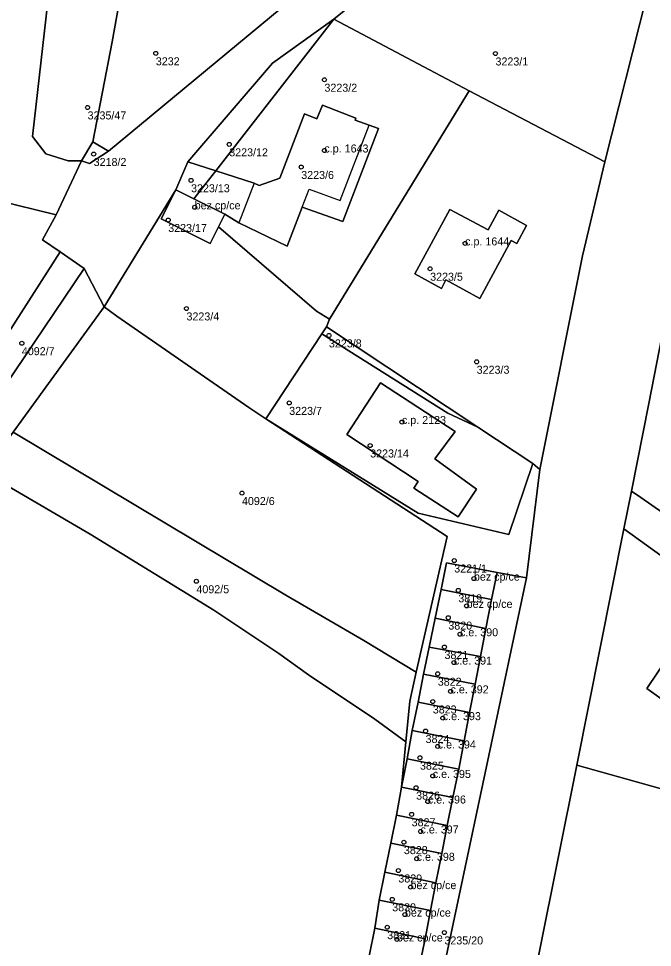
# Model space of a CAD drawing. Extents: x -878211 to -870363, y -1058464 to -1052522.
# Drawn here: x -875140.3 to -875061.1, y -1056719.1 to -1056603.1 of the extents above; entities that cross this region are included whole.
import ezdxf

# ---------------------------------------------------------------- set-up
doc = ezdxf.new("R2010")
doc.units = 0
for name, color, linetype in [('Definiční body', 7, 'Continuous'), ('Polygon budovy', 7, 'Continuous'), ('Polygon parcely', 7, 'Continuous')]:
    doc.layers.add(name, color=color, linetype=linetype)

msp = doc.modelspace()

# ---------------------------------------------------------------- linework, layer by layer
at = {"layer": 'Definiční body'}
for centre in [(-875123.14, -1056607.45994), (-875080.72, -1056607.47994), (-875102.08, -1056610.75994), (-875131.66, -1056614.21994), (-875113.97, -1056618.82994), (-875130.9, -1056620.03994), (-875102.08, -1056619.58994), (-875104.98, -1056621.65994), (-875118.74, -1056623.31994), (-875118.28, -1056626.68994), (-875121.59, -1056628.27994), (-875084.51, -1056631.19994), (-875088.88, -1056634.36994), (-875119.31, -1056639.32994), (-875101.52, -1056642.69994), (-875139.87, -1056643.66994), (-875083.07, -1056645.98994), (-875106.48, -1056651.12994), (-875092.4, -1056653.50994), (-875096.37, -1056656.44994), (-875112.38, -1056662.38994), (-875085.87, -1056670.81994), (-875118.07, -1056673.40994), (-875083.41, -1056673.06994), (-875085.36, -1056674.53994), (-875084.32, -1056676.47994), (-875086.61, -1056677.94994), (-875085.15, -1056680.01994), (-875087.09, -1056681.61994), (-875085.91, -1056683.55994), (-875087.93, -1056684.95994), (-875086.33, -1056687.15994), (-875088.55, -1056688.42994), (-875087.3, -1056690.49994), (-875089.45, -1056692.10994), (-875087.93, -1056694.03994), (-875090.15, -1056695.44994), (-875088.55, -1056697.71994), (-875090.63, -1056699.18994), (-875089.17, -1056700.91994), (-875091.19, -1056702.51994), (-875090.08, -1056704.65994), (-875092.16, -1056705.99994), (-875090.56, -1056708.06994), (-875092.85, -1056709.53994), (-875091.33, -1056711.60994), (-875093.62, -1056713.13994), (-875092.02, -1056715.03994), (-875094.24, -1056716.61994), (-875087.1, -1056717.27994), (-875093.03, -1056718.14994)]:
    msp.add_circle(centre, 0.25, dxfattribs=at)
at = {"layer": 'Polygon budovy'}
for points in [[(-875098.17, -1056615.55), (-875102.34, -1056613.94), (-875103.02, -1056615.62), (-875104.57, -1056615.01), (-875107.67, -1056623.06), (-875110.23, -1056623.95), (-875110.84, -1056623.69), (-875112.76, -1056628.63), (-875106.72, -1056631.55), (-875104.85, -1056626.68), (-875103.98, -1056624.42), (-875100.12, -1056625.85), (-875096.51, -1056616.44), (-875098.25, -1056615.79)], [(-875120.62, -1056624.51), (-875122.46, -1056628.14), (-875116.34, -1056631.22), (-875115.29, -1056629.12), (-875114.51, -1056627.56), (-875118.38, -1056625.63)], [(-875086.4, -1056626.95), (-875090.81, -1056635.01), (-875087.48, -1056636.81), (-875086.9, -1056635.74), (-875082.66, -1056638.07), (-875078.75, -1056630.82), (-875078.05, -1056631.2), (-875076.84, -1056628.96), (-875080.32, -1056627.03), (-875081.64, -1056629.5)], [(-875095.06, -1056648.6), (-875099.29, -1056655.07), (-875090.38, -1056660.94), (-875090.93, -1056661.77), (-875085.38, -1056665.36), (-875083.1, -1056661.9), (-875088.29, -1056658.09), (-875085.76, -1056654.68)], [(-875086.83, -1056671.12), (-875087.51, -1056674.45), (-875081.22, -1056675.66), (-875080.52, -1056672.32)], [(-875088.24, -1056678.03), (-875081.93, -1056679.3), (-875081.22, -1056675.66), (-875087.51, -1056674.45)], [(-875088.99, -1056681.62), (-875082.61, -1056682.78), (-875081.93, -1056679.3), (-875088.24, -1056678.03)], [(-875046.32, -1056685), (-875044.88, -1056682.91), (-875046.64, -1056681.74), (-875048.06, -1056683.83), (-875056.14, -1056678.39), (-875061.81, -1056686.81), (-875059.04, -1056688.8), (-875059.07, -1056689.09), (-875048.31, -1056696.37), (-875048.14, -1056696.15), (-875045.19, -1056698.06), (-875039.56, -1056689.55)], [(-875088.99, -1056681.62), (-875089.73, -1056685.01), (-875083.27, -1056686.24), (-875082.61, -1056682.78)], [(-875090.36, -1056688.49), (-875083.97, -1056689.81), (-875083.27, -1056686.24), (-875089.73, -1056685.01)], [(-875084.65, -1056693.35), (-875083.97, -1056689.81), (-875090.36, -1056688.49), (-875091.11, -1056692.06)], [(-875091.75, -1056695.59), (-875085.31, -1056696.89), (-875084.65, -1056693.35), (-875091.11, -1056692.06)], [(-875091.75, -1056695.59), (-875092.44, -1056699.14), (-875086.03, -1056700.41), (-875085.31, -1056696.89)], [(-875093.1, -1056702.61), (-875086.74, -1056703.92), (-875086.03, -1056700.41), (-875092.44, -1056699.14)], [(-875093.1, -1056702.61), (-875093.77, -1056706.12), (-875087.41, -1056707.4), (-875086.74, -1056703.92)], [(-875094.52, -1056709.74), (-875088.16, -1056711.08), (-875087.41, -1056707.4), (-875093.77, -1056706.12)], [(-875094.52, -1056709.74), (-875095.25, -1056713.24), (-875088.82, -1056714.54), (-875088.16, -1056711.08)], [(-875095.8, -1056716.75), (-875089.5, -1056718.06), (-875088.82, -1056714.54), (-875095.25, -1056713.24)], [(-875095.8, -1056716.75), (-875096.5, -1056720.24), (-875090.24, -1056721.62), (-875089.5, -1056718.06)]]:
    msp.add_lwpolyline(points, close=True, dxfattribs=at)
at = {"layer": 'Polygon parcely'}
for points in [[(-874975.13, -1056393.67), (-874980.45, -1056410.63), (-874983.57, -1056424.89), (-875001.65, -1056483.66), (-875005.15, -1056492.08), (-875032.55, -1056540.02), (-875035.19, -1056534.63), (-875039.79, -1056543.8), (-875051.68, -1056572.91), (-875052.45, -1056574.91), (-875061.84, -1056600.38), (-875067.07, -1056621.01), (-875069.87, -1056632.77), (-875075.2, -1056659.42), (-875076.83, -1056672.97), (-875088.05, -1056725.8)], [(-875147.44, -1056651.53), (-875135.09, -1056632.27), (-875137.28, -1056630.77), (-875135.57, -1056627.63), (-875150.54, -1056623.98)], [(-875079.85, -1056742.65), (-875070.58, -1056696.36), (-875064.69, -1056666.87), (-875063.74, -1056662.13), (-875061.56, -1056651.21), (-875058, -1056632.84)], [(-875096.5, -1056720.24), (-875095.8, -1056716.75), (-875095.25, -1056713.24), (-875094.52, -1056709.74), (-875093.77, -1056706.12), (-875093.1, -1056702.61), (-875092.44, -1056699.14), (-875091.91, -1056693.44), (-875095.8, -1056690.63), (-875104.09, -1056685.1), (-875107.77, -1056682.42), (-875115.91, -1056677.03), (-875131.33, -1056667.53), (-875144.62, -1056659.79)], [(-875052, -1056670.3), (-875062.58, -1056662.94), (-875063.74, -1056662.13), (-875064.69, -1056666.87), (-875061.87, -1056668.91), (-875054.13, -1056674.49)], [(-875088.05, -1056725.8), (-875076.83, -1056672.97), (-875080.52, -1056672.32), (-875081.22, -1056675.66), (-875081.93, -1056679.3), (-875082.61, -1056682.78), (-875083.27, -1056686.24), (-875083.97, -1056689.81), (-875084.65, -1056693.35), (-875085.31, -1056696.89), (-875086.03, -1056700.41), (-875086.74, -1056703.92), (-875087.41, -1056707.4), (-875088.16, -1056711.08), (-875088.82, -1056714.54), (-875089.5, -1056718.06), (-875090.24, -1056721.62)]]:
    msp.add_lwpolyline(points, dxfattribs=at)
for points in [[(-875132.07, -1056634.34), (-875129.58, -1056639.14), (-875120.62, -1056624.51), (-875119.16, -1056621.01), (-875108.56, -1056608.67), (-875100.9, -1056603.18), (-875092.92, -1056596.72), (-875079.96, -1056589.72), (-875078.48, -1056587.09), (-875068.77, -1056576.4), (-875069.25, -1056570.23), (-875083.66, -1056582.09), (-875092.7, -1056589.53), (-875129.03, -1056619.67), (-875131.42, -1056621.2), (-875132.43, -1056620.89), (-875135.57, -1056627.63), (-875137.28, -1056630.77), (-875135.09, -1056632.27)], [(-875092.7, -1056589.53), (-875105.74, -1056586.1), (-875107.74, -1056599.08), (-875118.83, -1056597.36), (-875117.58, -1056589.47), (-875125.11, -1056588.01), (-875127.7, -1056601.16), (-875128.61, -1056606.02), (-875131.01, -1056618.5), (-875129.03, -1056619.67)], [(-875092.92, -1056596.72), (-875100.9, -1056603.18), (-875084.01, -1056612.14), (-875067.07, -1056621.01), (-875061.84, -1056600.38), (-875072.18, -1056596.84), (-875070.92, -1056593.21), (-875074.27, -1056592.01), (-875079.61, -1056589.86), (-875079.96, -1056589.72)], [(-875136.63, -1056600.96), (-875236.32, -1056602.29), (-875236.35, -1056608.98), (-875235.7, -1056613.74), (-875221.55, -1056617.25), (-875208.62, -1056621), (-875196.21, -1056625.52), (-875183.08, -1056631.34), (-875173.25, -1056636.71), (-875161.79, -1056643.58), (-875150.54, -1056623.98), (-875135.57, -1056627.63), (-875132.43, -1056620.89), (-875134.07, -1056620.89), (-875136.87, -1056620), (-875138.55, -1056617.84)], [(-875138.55, -1056617.84), (-875136.87, -1056620), (-875134.07, -1056620.89), (-875132.43, -1056620.89), (-875131.01, -1056618.5), (-875128.61, -1056606.02), (-875127.7, -1056601.16), (-875136.63, -1056600.96)], [(-875115.66, -1056622.14), (-875100.9, -1056603.18), (-875108.56, -1056608.67), (-875119.16, -1056621.01)], [(-875114.51, -1056627.56), (-875115.29, -1056629.12), (-875103.09, -1056639.66), (-875101.43, -1056640.66), (-875084.01, -1056612.14), (-875100.9, -1056603.18), (-875115.66, -1056622.14), (-875110.84, -1056623.69), (-875110.23, -1056623.95), (-875107.67, -1056623.06), (-875104.57, -1056615.01), (-875103.02, -1056615.62), (-875102.34, -1056613.94), (-875098.17, -1056615.55), (-875098.25, -1056615.79), (-875096.51, -1056616.44), (-875095.33, -1056616.86), (-875099.8, -1056628.45), (-875104.85, -1056626.68), (-875106.72, -1056631.55), (-875112.76, -1056628.63)], [(-875076.07, -1056658.7), (-875075.2, -1056659.42), (-875069.87, -1056632.77), (-875067.07, -1056621.01), (-875084.01, -1056612.14), (-875101.43, -1056640.66), (-875101.81, -1056641.6), (-875082.94, -1056654.17)], [(-875118.38, -1056625.63), (-875114.51, -1056627.56), (-875112.76, -1056628.63), (-875106.72, -1056631.55), (-875104.85, -1056626.68), (-875099.8, -1056628.45), (-875095.33, -1056616.86), (-875096.51, -1056616.44), (-875098.25, -1056615.79), (-875098.17, -1056615.55), (-875102.34, -1056613.94), (-875103.02, -1056615.62), (-875104.57, -1056615.01), (-875107.67, -1056623.06), (-875110.23, -1056623.95), (-875110.84, -1056623.69), (-875115.66, -1056622.14)], [(-875132.43, -1056620.89), (-875131.42, -1056621.2), (-875129.03, -1056619.67), (-875131.01, -1056618.5)], [(-875120.62, -1056624.51), (-875118.38, -1056625.63), (-875115.66, -1056622.14), (-875119.16, -1056621.01)], [(-875128.02, -1056640.29), (-875111.51, -1056651.71), (-875109.41, -1056653.11), (-875102.41, -1056642.51), (-875101.81, -1056641.6), (-875101.43, -1056640.66), (-875103.09, -1056639.66), (-875115.29, -1056629.12), (-875116.34, -1056631.22), (-875122.46, -1056628.14), (-875120.62, -1056624.51), (-875129.58, -1056639.14)], [(-875120.62, -1056624.51), (-875122.46, -1056628.14), (-875116.34, -1056631.22), (-875115.29, -1056629.12), (-875114.51, -1056627.56), (-875118.38, -1056625.63)], [(-875087.48, -1056636.81), (-875086.9, -1056635.74), (-875082.66, -1056638.07), (-875078.75, -1056630.82), (-875078.05, -1056631.2), (-875076.84, -1056628.96), (-875080.32, -1056627.03), (-875081.64, -1056629.5), (-875086.4, -1056626.95), (-875090.81, -1056635.01)], [(-875087.48, -1056636.81), (-875090.81, -1056635.01), (-875086.4, -1056626.95), (-875081.64, -1056629.5), (-875080.32, -1056627.03), (-875076.84, -1056628.96), (-875078.05, -1056631.2), (-875078.75, -1056630.82), (-875082.66, -1056638.07), (-875086.9, -1056635.74)], [(-875147.44, -1056651.53), (-875144.63, -1056652.87), (-875132.07, -1056634.34), (-875135.09, -1056632.27)], [(-875054.2, -1056635.62), (-875058, -1056632.84), (-875061.56, -1056651.21), (-875063.74, -1056662.13), (-875062.58, -1056662.94), (-875052, -1056670.3), (-875031.7, -1056677.75), (-874994.36, -1056690.62), (-874969.93, -1056695.59), (-874964.18, -1056690.59), (-874960.32, -1056681.28), (-874969.59, -1056675.5), (-874970.83, -1056674.71), (-874976.58, -1056671.11), (-874979.49, -1056669.39), (-874981.46, -1056668.14), (-875047.89, -1056640.23)], [(-875158.29, -1056678.56), (-875144.62, -1056659.79), (-875140.97, -1056654.78), (-875129.58, -1056639.14), (-875132.07, -1056634.34), (-875144.63, -1056652.87), (-875148.03, -1056657.88), (-875152.95, -1056665.14)], [(-875090.61, -1056684.77), (-875086.74, -1056667.79), (-875109.41, -1056653.11), (-875111.51, -1056651.71), (-875128.02, -1056640.29), (-875129.58, -1056639.14), (-875140.97, -1056654.78), (-875106.91, -1056675.12), (-875097.17, -1056680.82)], [(-875082.94, -1056654.17), (-875101.81, -1056641.6), (-875102.41, -1056642.51), (-875086.67, -1056652.4)], [(-875086.67, -1056652.4), (-875102.41, -1056642.51), (-875109.41, -1056653.11), (-875090.39, -1056664.91), (-875079.06, -1056667.56), (-875076.07, -1056658.7), (-875082.94, -1056654.17)], [(-875090.93, -1056661.77), (-875085.38, -1056665.36), (-875083.1, -1056661.9), (-875088.29, -1056658.09), (-875085.76, -1056654.68), (-875095.06, -1056648.6), (-875099.29, -1056655.07), (-875090.38, -1056660.94)], [(-875090.93, -1056661.77), (-875090.38, -1056660.94), (-875099.29, -1056655.07), (-875095.06, -1056648.6), (-875085.76, -1056654.68), (-875088.29, -1056658.09), (-875083.1, -1056661.9), (-875085.38, -1056665.36)], [(-875091.91, -1056693.44), (-875092.44, -1056699.14), (-875091.75, -1056695.59), (-875091.11, -1056692.06), (-875090.36, -1056688.49), (-875089.73, -1056685.01), (-875088.99, -1056681.62), (-875088.24, -1056678.03), (-875087.51, -1056674.45), (-875086.83, -1056671.12), (-875080.52, -1056672.32), (-875076.83, -1056672.97), (-875075.2, -1056659.42), (-875076.07, -1056658.7), (-875079.06, -1056667.56), (-875090.39, -1056664.91), (-875109.41, -1056653.11), (-875086.74, -1056667.79), (-875090.61, -1056684.77), (-875091.43, -1056688.36)], [(-875090.61, -1056684.77), (-875097.17, -1056680.82), (-875106.91, -1056675.12), (-875140.97, -1056654.78), (-875144.62, -1056659.79), (-875131.33, -1056667.53), (-875115.91, -1056677.03), (-875107.77, -1056682.42), (-875104.09, -1056685.1), (-875095.8, -1056690.63), (-875091.91, -1056693.44), (-875091.43, -1056688.36)], [(-875033.98, -1056681.51), (-875054.13, -1056674.49), (-875061.87, -1056668.91), (-875064.69, -1056666.87), (-875070.58, -1056696.36), (-874971.25, -1056724.17), (-874965.51, -1056725.78), (-874958.57, -1056727.67), (-874952.5, -1056725.13), (-874945.84, -1056719.49), (-874939.85, -1056712.99), (-874937.64, -1056707.11), (-874938.78, -1056706.6), (-874939.54, -1056709.59), (-874960.23, -1056695.82), (-874961.04, -1056695.28), (-874963.53, -1056701.5), (-874995.69, -1056695.3)], [(-875081.22, -1056675.66), (-875080.52, -1056672.32), (-875086.83, -1056671.12), (-875087.51, -1056674.45)], [(-875088.24, -1056678.03), (-875081.93, -1056679.3), (-875081.22, -1056675.66), (-875087.51, -1056674.45)], [(-875082.61, -1056682.78), (-875081.93, -1056679.3), (-875088.24, -1056678.03), (-875088.99, -1056681.62)], [(-875039.56, -1056689.55), (-875045.19, -1056698.06), (-875048.14, -1056696.15), (-875048.31, -1056696.37), (-875059.07, -1056689.09), (-875059.04, -1056688.8), (-875061.81, -1056686.81), (-875056.14, -1056678.39), (-875048.06, -1056683.83), (-875046.64, -1056681.74), (-875044.88, -1056682.91), (-875046.32, -1056685)], [(-875039.56, -1056689.55), (-875046.32, -1056685), (-875044.88, -1056682.91), (-875046.64, -1056681.74), (-875048.06, -1056683.83), (-875056.14, -1056678.39), (-875061.81, -1056686.81), (-875059.04, -1056688.8), (-875059.07, -1056689.09), (-875048.31, -1056696.37), (-875048.14, -1056696.15), (-875045.19, -1056698.06)], [(-875083.27, -1056686.24), (-875082.61, -1056682.78), (-875088.99, -1056681.62), (-875089.73, -1056685.01)], [(-875090.36, -1056688.49), (-875083.97, -1056689.81), (-875083.27, -1056686.24), (-875089.73, -1056685.01)], [(-875084.65, -1056693.35), (-875083.97, -1056689.81), (-875090.36, -1056688.49), (-875091.11, -1056692.06)], [(-875091.75, -1056695.59), (-875085.31, -1056696.89), (-875084.65, -1056693.35), (-875091.11, -1056692.06)], [(-875086.62, -1056776.65), (-875097.04, -1056808.99), (-875096.89, -1056816.97), (-875060.2, -1056830.88), (-875017.6, -1056842.12), (-874988.92, -1056847.01), (-874988.71, -1056845.15), (-874986.17, -1056827.14), (-874985.74, -1056823.88), (-874982.68, -1056800.77), (-874979, -1056778.71), (-874977.65, -1056766.28), (-874974.89, -1056749.21), (-874974.26, -1056745.05), (-874971.25, -1056724.17), (-875070.58, -1056696.36), (-875079.85, -1056742.65), (-875077.16, -1056744.23)], [(-875086.03, -1056700.41), (-875085.31, -1056696.89), (-875091.75, -1056695.59), (-875092.44, -1056699.14)], [(-875092.44, -1056699.14), (-875093.1, -1056702.61), (-875086.74, -1056703.92), (-875086.03, -1056700.41)], [(-875093.77, -1056706.12), (-875087.41, -1056707.4), (-875086.74, -1056703.92), (-875093.1, -1056702.61)], [(-875093.77, -1056706.12), (-875094.52, -1056709.74), (-875088.16, -1056711.08), (-875087.41, -1056707.4)], [(-875095.25, -1056713.24), (-875088.82, -1056714.54), (-875088.16, -1056711.08), (-875094.52, -1056709.74)], [(-875095.25, -1056713.24), (-875095.8, -1056716.75), (-875089.5, -1056718.06), (-875088.82, -1056714.54)], [(-875096.5, -1056720.24), (-875090.24, -1056721.62), (-875089.5, -1056718.06), (-875095.8, -1056716.75)]]:
    msp.add_lwpolyline(points, close=True, dxfattribs=at)

# ---------------------------------------------------------------- texts
at = {"layer": 'Definiční body'}
for s, p in [('3232', (-875123.14, -1056608.949)), ('3223/1', (-875080.72, -1056608.969)), ('3223/2', (-875102.08, -1056612.249)), ('3235/47', (-875131.66, -1056615.709)), ('3223/12', (-875113.97, -1056620.319)), ('c.p. 1643', (-875102.08, -1056619.84)), ('3218/2', (-875130.9, -1056621.529)), ('3223/6', (-875104.98, -1056623.149)), ('3223/13', (-875118.74, -1056624.809)), ('bez cp/ce', (-875118.28, -1056626.94)), ('3223/17', (-875121.59, -1056629.769)), ('c.p. 1644', (-875084.51, -1056631.45)), ('3223/5', (-875088.88, -1056635.859)), ('3223/4', (-875119.31, -1056640.819)), ('3223/8', (-875101.52, -1056644.189)), ('4092/7', (-875139.87, -1056645.159)), ('3223/3', (-875083.07, -1056647.479)), ('3223/7', (-875106.48, -1056652.619)), ('c.p. 2123', (-875092.4, -1056653.76)), ('3223/14', (-875096.37, -1056657.939)), ('4092/6', (-875112.38, -1056663.879)), ('3221/1', (-875085.87, -1056672.309)), ('bez cp/ce', (-875083.41, -1056673.32)), ('4092/5', (-875118.07, -1056674.899)), ('3819', (-875085.36, -1056676.029)), ('bez cp/ce', (-875084.32, -1056676.73)), ('3820', (-875086.61, -1056679.439)), ('c.e. 390', (-875085.15, -1056680.27)), ('3821', (-875087.09, -1056683.109)), ('c.e. 391', (-875085.91, -1056683.81)), ('3822', (-875087.93, -1056686.449)), ('c.e. 392', (-875086.33, -1056687.409)), ('3823', (-875088.55, -1056689.919)), ('c.e. 393', (-875087.3, -1056690.75)), ('3824', (-875089.45, -1056693.599)), ('c.e. 394', (-875087.93, -1056694.29)), ('3825', (-875090.15, -1056696.939)), ('c.e. 395', (-875088.55, -1056697.97)), ('3826', (-875090.63, -1056700.679)), ('c.e. 396', (-875089.17, -1056701.169)), ('3827', (-875091.19, -1056704.009)), ('c.e. 397', (-875090.08, -1056704.909)), ('3828', (-875092.16, -1056707.489)), ('c.e. 398', (-875090.56, -1056708.32)), ('3829', (-875092.85, -1056711.029)), ('bez cp/ce', (-875091.33, -1056711.86)), ('3830', (-875093.62, -1056714.629)), ('bez cp/ce', (-875092.02, -1056715.29)), ('3831', (-875094.24, -1056718.109)), ('bez cp/ce', (-875093.03, -1056718.399)), ('3235/20', (-875087.1, -1056718.769))]:
    msp.add_text(s, height=0.999996, dxfattribs=at).set_placement(p)

doc.saveas('drawing.dxf')
